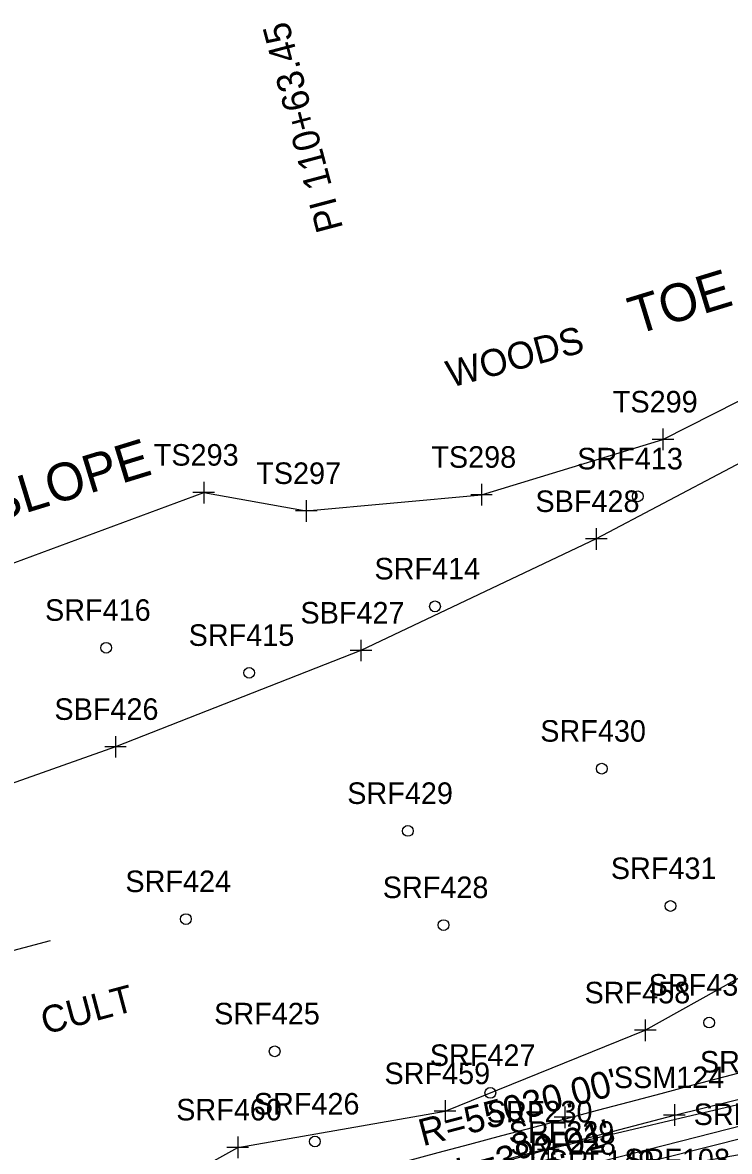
# Model space of a CAD drawing. Extents: x 818717 to 846077, y 440014 to 541392.
# Drawn here: x 831879.9 to 832011.2, y 493204.5 to 493414 of the extents above; entities that cross this region are included whole.
import ezdxf

# ---------------------------------------------------------------- set-up
doc = ezdxf.new("R2010")
doc.units = 0
for name, color, linetype in [('SURVEY - CENTERLINE - Preliminary', 7, 'Continuous'), ('SURVEY - CENTERLINE - Preliminary Curve Text', 7, 'Continuous'), ('SURVEY - DTM - Breaklines', 7, 'Continuous'), ('SURVEY - DTM - Breaklines - Points - Locators', 7, 'Continuous'), ('SURVEY - DTM - Breaklines - Points - Numbers', 7, 'Continuous'), ('SURVEY - DTM - Spot Points - Locators', 7, 'Continuous'), ('SURVEY - DTM - Spot Points - Point Numbers', 7, 'Continuous'), ('SURVEY - PROPERTY - ROW Lines', 7, 'Continuous'), ('SURVEY - PROPERTY - ROW Lines - Points - Locators', 7, 'Continuous'), ('SURVEY - PROPERTY - ROW Lines Text', 7, 'Continuous'), ('SURVEY - TRANSPORTATION - Roads - Points - Numbers', 7, 'Continuous'), ('SURVEY - UTILITIES - Water - Points - Locators', 7, 'Continuous'), ('SURVEY - UTILITIES - Water - Points - Numbers', 7, 'Continuous'), ('SURVEY - UTILITIES - Water with Text', 7, 'Continuous'), ('SURVEY - VEGETATION - Features - Points - Locators', 7, 'Continuous'), ('SURVEY - VEGETATION - Features - Points - Numbers', 7, 'Continuous'), ('SURVEY - VEGETATION - Features with Text', 7, 'Continuous')]:
    doc.layers.add(name, color=color, linetype=linetype)

msp = doc.modelspace()

# ---------------------------------------------------------------- linework, layer by layer
at = {"layer": 'SURVEY - CENTERLINE - Preliminary'}
msp.add_arc((846074.62, 440015.93), 55000, 104.635499, 105.043654, dxfattribs=at)
msp.add_arc((846074.62, 440015.93), 55000, 104.635499, 105.043654, dxfattribs=at)
msp.add_arc((846074.62, 440015.93), 55000, 104.635499, 105.043654, dxfattribs=at)
at = {"layer": 'SURVEY - DTM - Breaklines'}
for points in [[(831606.4, 493385.07), (831626.56, 493343.84), (831646.81, 493316.23), (831679.76, 493323.16), (831722.46, 493321.1), (831763.56, 493324.84), (831796.15, 493317.51), (831818.82, 493314.11), (831838.63, 493302.24), (831870.09, 493310.69), (831913.57, 493326.74), (831932.6, 493323.34), (831965.15, 493326.35), (831998.83, 493336.61), (832026.78, 493350.77), (832073.48, 493375.47)], [(832142.59, 493248.12), (832139.68, 493247.54), (832108.04, 493238.25), (832059.21, 493226.8), (832016.93, 493214.13), (831977.53, 493204.88), (831934.18, 493192.82), (831885.96, 493181.02), (831841.41, 493171.23), (831796.37, 493166.38), (831801.69, 493181.68), (831795.28, 493183.83), (831789.32, 493168.76), (831775.78, 493173.56), (831765.85, 493166.76)], [(832140.22, 493244.36), (832106.95, 493233.7), (832060.11, 493221.66), (832022.66, 493211.6), (831981.44, 493201.09), (831935.37, 493189.1), (831887.47, 493176.86), (831843.25, 493166.04), (831798.12, 493162.94), (831794.2, 493164.7), (831799.41, 493178.67), (831795.65, 493181.96), (831790.41, 493167.38)], [(832140.95, 493241.96), (832107.3, 493230.3), (832060.96, 493218.28), (832023.31, 493209.39), (831981.76, 493198.9), (831936.65, 493186.2), (831888.63, 493174.71), (831844.24, 493162.67), (831795, 493159.67)]]:
    msp.add_lwpolyline(points, dxfattribs=at)
at = {"layer": 'SURVEY - DTM - Breaklines - Points - Locators'}
for p, q in [((831998.83, 493338.61), (831998.83, 493334.61)), ((832000.83, 493336.61), (831996.83, 493336.61)), ((831913.57, 493328.74), (831913.57, 493324.74)), ((831965.15, 493328.35), (831965.15, 493324.35)), ((831915.57, 493326.74), (831911.57, 493326.74)), ((831967.15, 493326.35), (831963.15, 493326.35)), ((831932.6, 493325.34), (831932.6, 493321.34)), ((831934.6, 493323.34), (831930.6, 493323.34)), ((831977.53, 493206.88), (831977.53, 493202.88)), ((831979.53, 493204.88), (831975.53, 493204.88))]:
    msp.add_line(p, q, dxfattribs=at)
at = {"layer": 'SURVEY - DTM - Spot Points - Locators'}
for centre in [(831994.15, 493326.05), (831956.5, 493305.63), (831895.45, 493297.95), (831922, 493293.3), (831987.46, 493275.52), (831951.47, 493263.97), (832000.23, 493250.04), (831910.26, 493247.61), (831958.09, 493246.5), (832007.41, 493228.4), (831926.74, 493223.07), (831966.78, 493215.35), (831934.21, 493206.34)]:
    msp.add_circle(centre, 1, dxfattribs=at)
at = {"layer": 'SURVEY - PROPERTY - ROW Lines'}
msp.add_arc((846074.62, 440015.93), 55030, 104.635499, 105.043649, dxfattribs=at)
at = {"layer": 'SURVEY - PROPERTY - ROW Lines - Points - Locators'}
for p, q in [((831980.6, 493212.84), (831980.6, 493208.84)), ((831982.6, 493210.84), (831978.6, 493210.84))]:
    msp.add_line(p, q, dxfattribs=at)
at = {"layer": 'SURVEY - PROPERTY - ROW Lines Text'}
msp.add_line((831885.03, 493243.58), (831815.26, 493224.83), dxfattribs=at)
at = {"layer": 'SURVEY - UTILITIES - Water - Points - Locators'}
for p, q in [((832000.95, 493213.25), (832000.95, 493209.25)), ((832002.95, 493211.25), (831998.95, 493211.25))]:
    msp.add_line(p, q, dxfattribs=at)
at = {"layer": 'SURVEY - UTILITIES - Water with Text'}
msp.add_lwpolyline([(831168.53, 492982.83), (831221.68, 492997.59), (831271.35, 493010.03), (831320.05, 493023.02), (831382.11, 493039.09), (831464.43, 493059.02), (831521.6, 493075.98), (831637.27, 493105.47), (831699.54, 493130.69), (831734.63, 493142.29), (831763.92, 493149.4), (831800.53, 493157.83), (831844.47, 493169.57), (831878.73, 493177.18), (831933.72, 493193.59), (832000.95, 493211.25), (832058.59, 493225.48), (832113.6, 493238.29), (832172.68, 493261.93), (832217.98, 493273.66), (832269.17, 493287.2), (832330.79, 493299.45)], dxfattribs=at)
at = {"layer": 'SURVEY - VEGETATION - Features - Points - Locators'}
for p, q in [((831986.44, 493320.14), (831986.44, 493316.14)), ((831988.44, 493318.14), (831984.44, 493318.14)), ((831942.76, 493299.45), (831942.76, 493295.45)), ((831944.76, 493297.45), (831940.76, 493297.45)), ((831899.19, 493279.57), (831895.19, 493279.57)), ((831897.19, 493281.57), (831897.19, 493277.57)), ((831995.55, 493228.97), (831995.55, 493224.97)), ((831997.55, 493226.97), (831993.55, 493226.97)), ((831958.38, 493213.98), (831958.38, 493209.98)), ((831960.38, 493211.98), (831956.38, 493211.98)), ((831919.88, 493207.25), (831919.88, 493203.25)), ((831921.88, 493205.25), (831917.88, 493205.25))]:
    msp.add_line(p, q, dxfattribs=at)
at = {"layer": 'SURVEY - VEGETATION - Features with Text'}
for points in [[(832074.38, 493372.96), (832067.41, 493358.76), (832023.76, 493337.86), (831986.44, 493318.14), (831942.76, 493297.45), (831897.19, 493279.57), (831855.2, 493264.73), (831811.79, 493246.68), (831803.11, 493234.77), (831807.59, 493210.38), (831821.29, 493179.51), (831838.37, 493176.64), (831840.42, 493162.7), (831816.2, 493152.67), (831768.47, 493143.37), (831736.25, 493132.08), (831689.16, 493118.85), (831643.12, 493105.66), (831600.48, 493097.11)], [(831888.55, 493177.45), (831886.32, 493186.52), (831919.88, 493205.25), (831958.38, 493211.98), (831995.55, 493226.97), (832045.5, 493254.8), (832112.46, 493247.88), (832111.49, 493228.36), (832055.54, 493211.96), (832015.77, 493204.39), (831965.98, 493195.44), (831889.31, 493176.37)]]:
    msp.add_lwpolyline(points, dxfattribs=at)

# ---------------------------------------------------------------- texts
at = {"layer": 'SURVEY - CENTERLINE - Preliminary Curve Text'}
msp.add_text('PI 110+63.45', height=5, rotation=104.8396, dxfattribs=at).set_placement((831939.48, 493375.81))
at = {"layer": 'SURVEY - DTM - Breaklines'}
for p in [(831993.78, 493355.99), (831838.61, 493310.09)]:
    msp.add_text('TOE OF SLOPE', height=7, rotation=17.0237, dxfattribs=at).set_placement(p)
at = {"layer": 'SURVEY - DTM - Breaklines - Points - Numbers'}
for s, p in [('TS299', (831989.52, 493341.61)), ('TS293', (831904.29, 493331.74)), ('TS298', (831955.82, 493331.35)), ('TS297', (831923.31, 493328.34)), ('SRF227', (832005.69, 493219.13)), ('SRF230', (831966.12, 493209.88)), ('SRF229', (831970.18, 493206.09)), ('SRF228', (831970.48, 493203.9)), ('SRF149', (831977.6, 493200.72))]:
    msp.add_text(s, height=4, dxfattribs=at).set_placement(p)
at = {"layer": 'SURVEY - DTM - Spot Points - Point Numbers'}
for s, p in [('SRF413', (831982.91, 493331.05)), ('SRF414', (831945.26, 493310.63)), ('SRF416', (831884.1, 493302.95)), ('SRF415', (831910.76, 493298.3)), ('SRF430', (831976.05, 493280.52)), ('SRF429', (831940.21, 493268.97)), ('SRF431', (831989.15, 493255.04)), ('SRF424', (831899.02, 493252.61)), ('SRF428', (831946.8, 493251.5)), ('SRF432', (831996.17, 493233.4)), ('SRF425', (831915.5, 493228.07)), ('SRF427', (831955.54, 493220.35)), ('SRF426', (831922.86, 493211.34))]:
    msp.add_text(s, height=4, dxfattribs=at).set_placement(p)
at = {"layer": 'SURVEY - PROPERTY - ROW Lines Text'}
for s, p in [("R=55030.00'", (831954.26, 493205.44)), ("L=392.01'", (831961.21, 493198.23))]:
    msp.add_text(s, height=5, rotation=14.8396, dxfattribs=at).set_placement(p)
at = {"layer": 'SURVEY - TRANSPORTATION - Roads - Points - Numbers'}
msp.add_text('SRF108', height=4, dxfattribs=at).set_placement((831991.65, 493200.99))
at = {"layer": 'SURVEY - UTILITIES - Water - Points - Numbers'}
msp.add_text('SSM124', height=4, dxfattribs=at).set_placement((831989.71, 493216.25))
at = {"layer": 'SURVEY - VEGETATION - Features - Points - Numbers'}
for s, p in [('SBF428', (831975.15, 493323.14)), ('SBF427', (831931.52, 493302.45)), ('SBF426', (831885.84, 493284.57)), ('SRF458', (831984.27, 493231.97)), ('SRF459', (831947.12, 493216.98)), ('SRF460', (831908.46, 493210.25)), ('SRF453', (832004.53, 493209.39))]:
    msp.add_text(s, height=4, dxfattribs=at).set_placement(p)
at = {"layer": 'SURVEY - VEGETATION - Features with Text'}
for s, rotation, p in [('WOODS', 14.951, (831959.41, 493346.19)), ('CULT', 14.9228, (831884.11, 493226.17))]:
    msp.add_text(s, height=5, rotation=rotation, dxfattribs=at).set_placement(p)

doc.saveas('drawing.dxf')
